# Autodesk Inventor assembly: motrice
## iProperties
Created: 2007-07
Part Number: motrice
Document SubType Name: Assembly
Designer: EF
Norme de conversion: STEP AP214IS
Nom du fichier: motrice.STEP
Préprocesseur: SolidWorks 2006104
Postprocesseur: Build: 254, Release: 2008 - Date: Fri 03/23/2007
Unités envoyées: MILLIMETERS
Incertitude: 1e-05
Author: EF
